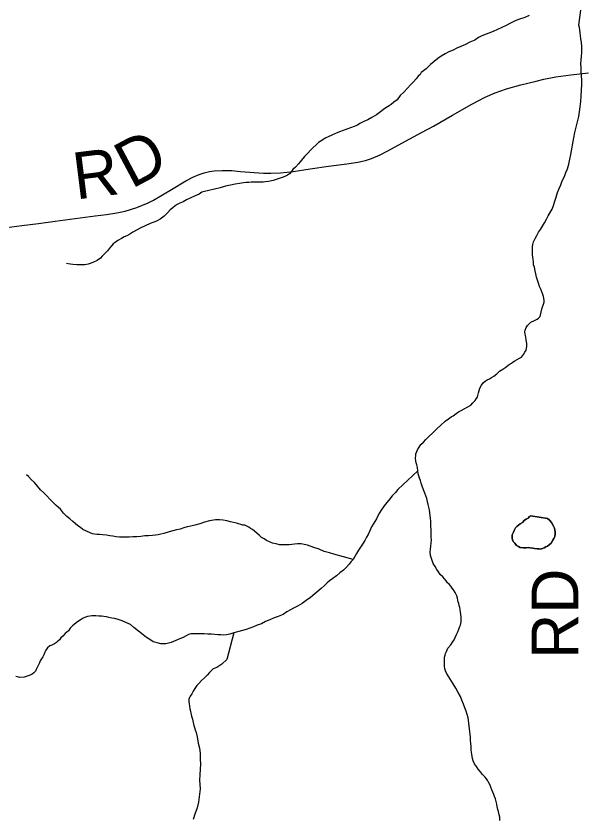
# Model space of a CAD drawing. Extents: x 103424 to 290657, y 38711 to 110967.
# Drawn here: x 115901 to 119588, y 79687 to 84863 of the extents above; entities that cross this region are included whole.
import ezdxf

# ---------------------------------------------------------------- set-up
doc = ezdxf.new("R2010")
doc.units = 0
for name, color, linetype in [('GM_X_Minor_Lake', 7, 'Continuous'), ('GM_X_Minor_River', 7, 'Continuous'), ('GM_X_Township_Road', 7, 'Continuous'), ('GM_X_Township_Road_Text', 7, 'Continuous')]:
    doc.layers.add(name, color=color, linetype=linetype)

msp = doc.modelspace()

# ---------------------------------------------------------------- linework, layer by layer
at = {"layer": 'GM_X_Minor_Lake'}
for points in [[(119225.9, 81636.5), (119217.7, 81632.3), (119207.7, 81622.1), (119195.6, 81615.9), (119185.6, 81607.8), (119171.7, 81593.5), (119157.6, 81585.3), (119145.6, 81577.1), (119135.6, 81568.9), (119127.6, 81558.7), (119117.7, 81542.4), (119113.8, 81530.3), (119105.9, 81514), (119104.2, 81491.8), (119106.3, 81481.7), (119112.5, 81471.7), (119122.7, 81459.7), (119133, 81445.6), (119145.2, 81437.7), (119157.4, 81431.7), (119177.6, 81429.9), (119195.8, 81430.1), (119207.9, 81432.2), (119220, 81430.3)], [(119225.9, 81636.5), (119332.9, 81619.3), (119345.2, 81609.3), (119359.5, 81593.3), (119369.8, 81575.2), (119378.1, 81557.1), (119380.3, 81545), (119382.4, 81533), (119382.6, 81518.8), (119380.7, 81502.6), (119374.8, 81490.5), (119366.9, 81480.3), (119357, 81460), (119345, 81449.8), (119333, 81441.6), (119322.9, 81437.4), (119310.9, 81429.2), (119300.9, 81425.1), (119288.8, 81420.9), (119278.7, 81422.8), (119266.5, 81424.7), (119250.3, 81426.6), (119238.2, 81428.5), (119220, 81430.3), (119207.9, 81432.2), (119195.8, 81430.1), (119177.6, 81429.9), (119157.4, 81431.7), (119145.2, 81437.7), (119133, 81445.6), (119122.7, 81459.7), (119112.5, 81471.7), (119106.3, 81481.7), (119104.2, 81491.8), (119105.9, 81514), (119113.8, 81530.3), (119117.7, 81542.4), (119127.6, 81558.7), (119135.6, 81568.9), (119145.6, 81577.1), (119157.6, 81585.3), (119171.7, 81593.5), (119185.6, 81607.8), (119195.6, 81615.9), (119207.7, 81622.1), (119217.7, 81632.3), (119225.9, 81636.5)], [(119220, 81430.3), (119238.2, 81428.5), (119250.3, 81426.6), (119266.5, 81424.7), (119278.7, 81422.8), (119288.8, 81420.9), (119300.9, 81425.1), (119310.9, 81429.2), (119322.9, 81437.4), (119333, 81441.6), (119345, 81449.8), (119357, 81460), (119366.9, 81480.3), (119374.8, 81490.5), (119380.7, 81502.6), (119382.6, 81518.8), (119382.4, 81533), (119380.3, 81545), (119378.1, 81557.1), (119369.8, 81575.2), (119359.5, 81593.3), (119345.2, 81609.3), (119332.9, 81619.3), (119225.9, 81636.5)]]:
    msp.add_lwpolyline(points, dxfattribs=at)
at = {"layer": 'GM_X_Minor_River'}
for points in [[(119308.2, 83053.3), (119304.1, 83065.4), (119295.8, 83081.4), (119289.5, 83099.6), (119281.2, 83117.7), (119274.9, 83137.8), (119268.7, 83158), (119262.4, 83178.1), (119258.1, 83198.2), (119253.8, 83218.4), (119249.5, 83242.6), (119243.3, 83256.7), (119243.1, 83272.8), (119240.8, 83293), (119238.6, 83307.1), (119236.5, 83321.3), (119236.3, 83333.4), (119236.2, 83345.5), (119236, 83359.6), (119235.8, 83373.8), (119237.7, 83387.9), (119243.6, 83404.1), (119253.4, 83426.5), (119263.3, 83446.8), (119275.2, 83467.1), (119287.1, 83485.4), (119301, 83505.7), (119312.8, 83528.1), (119326.7, 83550.4), (119338.6, 83572.8), (119350.4, 83595.1), (119362.3, 83615.4), (119372.1, 83639.7), (119379.9, 83668.1), (119389.7, 83694.5), (119397.4, 83722.8), (119409.2, 83749.2), (119419, 83773.5), (119428.8, 83799.9), (119442.7, 83826.3), (119452.5, 83852.6), (119462.3, 83877), (119470, 83907.4), (119477.7, 83937.7), (119483.4, 83968.1), (119502.4, 84077.4), (119510, 84111.8), (119517.7, 84146.2), (119527.4, 84180.7), (119535.1, 84213.1), (119540.8, 84243.4), (119544.5, 84275.8), (119548.1, 84310.1), (119549.8, 84344.5), (119553.3, 84387), (119554.9, 84419.3), (119554.6, 84447.6), (119552.3, 84475.8), (119549.9, 84504.1), (119549.6, 84530.3), (119549.3, 84554.6), (119551.1, 84580.9), (119552.8, 84603.1), (119554.6, 84625.3), (119554.3, 84645.5), (119554.1, 84665.7), (119551.8, 84694), (119549.5, 84716.2), (119547.2, 84736.4), (119545, 84754.5), (119542.8, 84772.7), (119540.6, 84788.8), (119536.4, 84802.9), (119549.4, 84900)], [(119214.5, 84866.4), (119186.4, 84854), (119146.1, 84839.4), (119120, 84829.1), (119093.9, 84816.7), (119065.8, 84802.3), (119037.7, 84787.9), (119009.6, 84775.5), (118983.4, 84763.1), (118909, 84734.1), (118887, 84723.7), (118864.9, 84707.4), (118830.8, 84692.9), (118802.7, 84678.5), (118774.5, 84666.1), (118748.4, 84655.7), (118724.3, 84643.3), (118696.2, 84630.9), (118672.1, 84618.6), (118646, 84604.2), (118624, 84587.8), (118602, 84569.4), (118577.9, 84549), (118550, 84522.4), (118532, 84508.1), (118518, 84497.9), (118510, 84485.7), (118498, 84473.4), (118486.1, 84457.1), (118468.1, 84438.8), (118448.2, 84418.4), (118428.3, 84396), (118406.3, 84371.5), (118382.4, 84349), (118362.5, 84322.6), (118340.4, 84306.2), (118324.4, 84291.9), (118310.4, 84283.7), (118300.4, 84277.5), (118288.4, 84269.3), (118274.3, 84259.1), (118254.3, 84244.7), (118228.3, 84224.3), (118198.2, 84207.8), (118172.1, 84193.4), (118148, 84181.1), (118121.9, 84168.7), (118105.9, 84158.4), (118083.7, 84150.1), (118061.6, 84141.8), (118037.5, 84131.5), (117989.2, 84114.9), (117965.1, 84104.5), (117916.9, 84083.8), (117896.8, 84073.5), (117876.8, 84059.2), (117854.7, 84046.8), (117802.7, 83997.8), (117784.8, 83977.5), (117762.9, 83955), (117744.9, 83932.6), (117725, 83908.2), (117705.1, 83887.8), (117689.1, 83871.5), (117679.1, 83859.2), (117667.2, 83845), (117653.2, 83834.8), (117637.1, 83826.5), (117619, 83820.3), (117600.9, 83814), (117580.8, 83807.8), (117560.7, 83801.5), (117532.5, 83795.2), (117510.3, 83792.9), (117496.2, 83790.8), (117480, 83790.6)], [(117480, 83790.6), (117461.8, 83790.4), (117435.6, 83790.2), (117419.4, 83790), (117405.3, 83787.8), (117387.1, 83787.7), (117369, 83785.5), (117344.8, 83781.2), (117316.6, 83776.9), (117286.4, 83770.5), (117254.1, 83764.1), (117219.9, 83753.7), (117183.6, 83745.2), (117145.4, 83736.8), (117119.2, 83730.5), (117101.1, 83726.2), (117083, 83713.9), (117056.9, 83701.6), (117030.8, 83689.2), (117002.7, 83676.8), (116980.6, 83664.4), (116958.5, 83654.1), (116942.4, 83645.9), (116928.4, 83637.7), (116914.4, 83625.4), (116896.4, 83611.1), (116878.4, 83592.7), (116858.5, 83570.3), (116832.4, 83551.9), (116808.4, 83539.5), (116790.3, 83531.2), (116768.2, 83522.9), (116701.9, 83494), (116683.8, 83481.7), (116655.7, 83467.3), (116635.7, 83454.9), (116617.6, 83444.7), (116599.5, 83436.4), (116581.5, 83426.1), (116559.4, 83413.8), (116541.4, 83401.5), (116527.3, 83391.2), (116519.4, 83381.1), (116505.4, 83364.8), (116491.5, 83346.4), (116475.5, 83330.1), (116465.5, 83321.9), (116457.6, 83311.8), (116445.6, 83299.5), (116425.6, 83285.2), (116397.5, 83270.8), (116367.3, 83260.4), (116345.1, 83256.1), (116327, 83255.9), (116310.8, 83255.8), (116292.6, 83257.6), (116268.3, 83259.4), (116238, 83263.1), (116227.8, 83265.6)], [(118607.4, 81309.1), (118595.1, 81329.2), (118578.3, 81381.5), (118576.1, 81403.7), (118577.9, 81421.9), (118579.7, 81440.1), (118581.4, 81462.4), (118583.2, 81480.6), (118583, 81500.8), (118582.8, 81521), (118582.5, 81545.2), (118580.2, 81571.4), (118579.8, 81601.7), (118575.4, 81638), (118570.9, 81674.4), (118562.4, 81710.6), (118553.9, 81748.9), (118541.4, 81783.1), (118526.8, 81821.4), (118518.4, 81847.6), (118512.1, 81865.7), (118505.9, 81879.8), (118501.7, 81893.9), (118497.5, 81908), (118495.3, 81926.1), (118493, 81948.3), (118488.7, 81966.4), (118484.6, 81978.5), (118482.4, 81990.6), (118480.2, 82010.8), (118482, 82022.9), (118483.9, 82037.1), (118489.8, 82051.3), (118493.7, 82063.5), (118503.6, 82079.7), (118515.5, 82098), (118531.5, 82112.3), (118547.5, 82128.6), (118565.4, 82147), (118595.4, 82173.5), (118619.4, 82198), (118645.3, 82222.5), (118671.3, 82247), (118693.3, 82263.4), (118711.4, 82275.7), (118723.4, 82281.9), (118743.4, 82298.2), (118757.4, 82308.5), (118775.5, 82316.7), (118837.7, 82351.7), (118851.7, 82366), (118865.7, 82380.3), (118873.6, 82392.5), (118881.6, 82402.6), (118883.5, 82412.8), (118887.3, 82431), (118891.2, 82445.2), (118897, 82461.4), (118906.9, 82479.7), (118918.8, 82495.9), (118930.8, 82506.2), (118942.9, 82514.4), (118959, 82520.6), (118971, 82528.8), (118987, 82539), (119005, 82553.4), (119023, 82569.7), (119045.1, 82584), (119063.1, 82596.3), (119079.1, 82608.6), (119091.1, 82616.8), (119101.2, 82623), (119111.2, 82631.2), (119123.2, 82637.3), (119137.3, 82645.6), (119153.3, 82653.8), (119165.4, 82660), (119179.3, 82678.3), (119187.2, 82692.5), (119195.1, 82706.7), (119198.9, 82729), (119198.7, 82749.2), (119196.4, 82771.4), (119194.1, 82791.6), (119189.9, 82809.7), (119187.7, 82823.8), (119189.6, 82836), (119195.4, 82852.2), (119203.4, 82864.4), (119213.4, 82874.6), (119225.3, 82886.8), (119249.5, 82897.2), (119265.5, 82905.4), (119275.5, 82911.6), (119285.5, 82923.8), (119299, 82978.5), (119304.8, 82996.7), (119310.7, 83014.9), (119312.6, 83027.1), (119310.4, 83041.2), (119308.2, 83053.3)], [(118077.8, 81354.3), (117954.2, 81389.4), (117925.8, 81397.3), (117891.4, 81407), (117858.9, 81420.8), (117824.4, 81432.6), (117783.9, 81446.3), (117761.6, 81452.2), (117741.4, 81456), (117719.1, 81455.8), (117699, 81453.6), (117682.8, 81451.4), (117664.7, 81449.2), (117650.5, 81449), (117634.4, 81448.9), (117620.3, 81448.8), (117602.1, 81450.6), (117581.8, 81456.4), (117557.5, 81460.2), (117537.2, 81468.1), (117518.9, 81478), (117502.7, 81488), (117486.4, 81497.9), (117470.1, 81511.9), (117427.3, 81547.8), (117415, 81555.8), (117404.8, 81563.8), (117390.6, 81569.7), (117378.5, 81575.6), (117366.3, 81577.5), (117352.1, 81581.4), (117338, 81585.3), (117323.8, 81589.2), (117305.6, 81593.1), (117285.3, 81598.9), (117263, 81604.8), (117238.7, 81608.6), (117214.5, 81610.4), (117188.2, 81610.1), (117149.9, 81603.6), (117117.7, 81595.2), (117087.5, 81584.8), (117055.3, 81576.4), (117029.1, 81570.1), (117007, 81565.9), (116984.8, 81559.6), (116960.7, 81551.3), (116936.5, 81547), (116914.4, 81540.7), (116890.2, 81532.4), (116856, 81521.9), (116835.9, 81517.7), (116819.8, 81513.5), (116801.6, 81511.3), (116781.4, 81509.1), (116757.2, 81506.8), (116733, 81506.6), (116706.8, 81504.3), (116680.5, 81502), (116656.3, 81501.8), (116632.1, 81499.5), (116611.9, 81499.3), (116587.7, 81499.1), (116569.5, 81498.9), (116547.3, 81500.7), (116527, 81504.5), (116506.8, 81508.4), (116484.5, 81512.2), (116460.3, 81514), (116440, 81515.8), (116421.9, 81515.6), (116407.7, 81517.5), (116395.6, 81521.4), (116379.3, 81527.3), (116332.6, 81549), (116316.3, 81561), (116300, 81573), (116283.7, 81586.9), (116267.4, 81600.9), (116249, 81616.9), (116228.7, 81632.8), (116208.2, 81652.9), (116187.7, 81678.9), (116159.2, 81702.9), (116138.7, 81724.9), (116118.3, 81744.9), (116099.9, 81764.9), (116079.5, 81784.9), (116059, 81804.9), (116040.6, 81828.9), (116020.1, 81850.9), (115999.7, 81870.9), (115981.3, 81891), (115968.5, 81902.1)], [(118495.3, 81926.1), (118367.4, 81805.6), (118351.5, 81787.3), (118329.5, 81764.9), (118307.6, 81738.4), (118285.7, 81709.9), (118263.9, 81679.4), (118244, 81648.9), (118228.2, 81618.4), (118208.4, 81581.9), (118196.5, 81565.6), (118190.6, 81551.4), (118182.7, 81535.2), (118174.9, 81516.9), (118165, 81498.6), (118153.1, 81478.3), (118139.2, 81453.9), (118125.3, 81433.6), (118113.4, 81415.3), (118099.6, 81392.9), (118089.7, 81374.6), (118077.8, 81354.3), (118063.8, 81340.1), (118051.9, 81323.8), (118035.9, 81305.4), (118016, 81287), (117991.9, 81268.6), (117969.9, 81250.2), (117945.9, 81231.8), (117925.9, 81217.5), (117909.9, 81203.2), (117889.9, 81184.8), (117871.9, 81168.4), (117801.9, 81109.2), (117773.9, 81090.7), (117747.8, 81070.2), (117719.8, 81053.8), (117693.6, 81041.4), (117673.6, 81029.1), (117649.5, 81016.8), (117625.5, 81000.4), (117593.3, 80987.9), (117567.2, 80977.6), (117541.1, 80965.2), (117512.9, 80954.8), (117486.8, 80940.4), (117458.6, 80930), (117434.5, 80919.7), (117410.4, 80911.4), (117386.3, 80903), (117364.1, 80896.8), (117340, 80890.5), (117307.7, 80882.1), (117281.6, 80873.7), (117259.4, 80869.4), (117241.3, 80867.2), (117223.1, 80869.1), (117204.9, 80868.9), (117184.7, 80870.7), (117162.4, 80872.5), (117140.2, 80872.3), (117116, 80874.1), (117093.7, 80875.9), (117073.5, 80875.7), (117045.3, 80875.4), (117029.1, 80875.2), (117015, 80871.1), (116999, 80862.8), (116980.9, 80852.5), (116962.8, 80844.3), (116948.8, 80838.1), (116932.7, 80831.8), (116918.6, 80825.7), (116902.5, 80819.4), (116886.4, 80815.2), (116868.3, 80811), (116854.2, 80810.9), (116836, 80810.7), (116811.7, 80816.5), (116787.4, 80824.3), (116765, 80838.3), (116744.6, 80852.2), (116722.2, 80868.1), (116661.1, 80916), (116640.7, 80936), (116610.2, 80947.8), (116585.9, 80959.7), (116561.5, 80967.5), (116539.2, 80973.4), (116519, 80977.2), (116500.8, 80981.1), (116484.6, 80984.9), (116468.4, 80986.8), (116452.2, 80988.7), (116436.1, 80988.5), (116415.9, 80990.3), (116391.6, 80992.1), (116377.5, 80989.9)], [(119026.3, 79671), (119026.1, 79691.2), (119021.9, 79707.3), (119017.6, 79727.5), (119013.4, 79741.6), (119009.1, 79759.7), (119006.9, 79775.8), (119000.7, 79794), (118996.4, 79810.1), (118990.2, 79824.2), (118986, 79838.2), (118979.8, 79852.3), (118973.5, 79868.4), (118967.3, 79884.5), (118963.1, 79898.6), (118954.9, 79912.7), (118948.6, 79926.8), (118938.4, 79938.8), (118928.1, 79952.8), (118913.8, 79966.8), (118899.5, 79984.8), (118885.2, 80000.9), (118874.8, 80018.9), (118862.5, 80037), (118854.2, 80055.1), (118848, 80071.2), (118843.6, 80097.4), (118841.3, 80123.6), (118841.1, 80147.9), (118838.8, 80168.1), (118836.5, 80188.2), (118836.3, 80208.4), (118834.1, 80226.6), (118831.8, 80244.8), (118829.6, 80262.9), (118827.4, 80281.1), (118825.2, 80297.2), (118822.9, 80317.4), (118820.7, 80333.5), (118814.4, 80353.7), (118808.1, 80375.8), (118799.8, 80398), (118791.4, 80422.1), (118781, 80446.3), (118770.7, 80470.4), (118756.2, 80496.5), (118741.8, 80524.6), (118723.3, 80552.7), (118680.1, 80621), (118673.8, 80637.1), (118669.6, 80651.2), (118667.4, 80665.3), (118667.2, 80685.5), (118667, 80705.7), (118668.8, 80723.9), (118672.6, 80738.1), (118674.5, 80748.2), (118680.5, 80760.4), (118690.3, 80782.7), (118708.2, 80803.1), (118720.1, 80821.4), (118730.1, 80835.6), (118738, 80851.9), (118745.8, 80870.1), (118753.7, 80888.4), (118759.6, 80904.6), (118765.5, 80918.8), (118771.4, 80931), (118773.3, 80941.1), (118775.2, 80953.2), (118775, 80971.4), (118774.8, 80985.5), (118772.6, 80999.7), (118772.4, 81015.8), (118770.2, 81032), (118766, 81046), (118763.8, 81058.2), (118759.7, 81070.2), (118755.5, 81082.3), (118753.3, 81092.4), (118751.2, 81104.5), (118747, 81120.6), (118740.8, 81132.7), (118736.6, 81142.7), (118726.3, 81158.8), (118718.1, 81170.8), (118707.9, 81182.8), (118697.6, 81194.9), (118687.4, 81204.9), (118679.2, 81216.9), (118668.9, 81230.9), (118656.7, 81242.9), (118640.3, 81258.9), (118630.1, 81275), (118617.8, 81291), (118607.4, 81309.1)], [(116377.5, 80989.9), (116363.4, 80987.8), (116349.3, 80981.6), (116335.2, 80975.4), (116321.2, 80967.2), (116305.2, 80956.9), (116289.1, 80946.6), (116277.1, 80936.4), (116265.1, 80926.2), (116251.2, 80911.9), (116239.3, 80893.6), (116219.3, 80877.3), (116203.3, 80860.9), (116191.3, 80848.7), (116181.4, 80836.5), (116171.3, 80828.3), (116163.4, 80818.1), (116149.4, 80809.9), (116131.3, 80801.6), (116119.2, 80797.5), (116103.2, 80785.2), (116093.3, 80768.9), (116087.4, 80756.8), (116081.5, 80740.5), (116073.6, 80726.3), (116065.6, 80714.1), (116057.7, 80701.9), (116051.8, 80687.7), (116032.1, 80645.1), (116026.2, 80635), (116016.2, 80622.7), (116006.2, 80614.6), (115992.1, 80608.3), (115974, 80602.1), (115953.9, 80595.8), (115925.7, 80593.5), (115911.5, 80597.4), (115899.4, 80599.3)], [(117307.7, 80882.1), (117263.3, 80709.9), (117229.3, 80679.3), (117197.2, 80658.7), (117175.1, 80648.4), (117165.1, 80640.2), (117151.2, 80626), (117135.2, 80607.6), (117117.2, 80591.3), (117099.3, 80572.9), (117081.3, 80554.6), (117069.3, 80542.3), (117055.4, 80522), (117045.5, 80505.7), (117035.6, 80487.5), (117025.7, 80473.2), (117021.8, 80463.1), (117017.9, 80452.9), (117018, 80436.8), (117018.2, 80424.7), (117020.4, 80408.5), (117022.6, 80390.4), (117026.8, 80376.3), (117029, 80362.1), (117033.3, 80344), (117039.6, 80323.9), (117045.9, 80303.7), (117050.1, 80283.6), (117054.3, 80269.5), (117058.5, 80255.4), (117064.8, 80237.3), (117071.2, 80211.1), (117077.7, 80168.7), (117086.2, 80136.5), (117090.6, 80104.2), (117091, 80065.8), (117091.4, 80033.5), (117089.7, 80001.2), (117088.2, 79964.8), (117086.5, 79930.4), (117088.9, 79902.2), (117089.2, 79873.9), (117080.1, 79789), (117070.4, 79752.5), (117056.7, 79712), (117045, 79677.5)]]:
    msp.add_lwpolyline(points, dxfattribs=at)
at = {"layer": 'GM_X_Township_Road'}
msp.add_lwpolyline([(115774.7, 83488.8), (115938.3, 83510.3), (116045.6, 83524.5), (116153, 83538.6), (116282.4, 83556.3), (116411.8, 83574), (116484.3, 83582.6), (116553, 83592), (116606.5, 83603), (116680.9, 83625.8), (116753.9, 83655.9), (116789, 83674.5), (116904.2, 83743.7), (116997.5, 83799.8), (117042.8, 83822.7), (117084.4, 83839.3), (117116.9, 83850.9), (117149.6, 83858.6), (117181.6, 83863.5), (117232.6, 83866.2), (117294.1, 83864.6), (117350.1, 83860.1), (117498.5, 83849.3), (117546.7, 83848.4), (117608, 83851.1), (117690.2, 83860), (117799.7, 83875.8), (117918.8, 83892.6), (118037.8, 83909.4), (118109.3, 83919.6), (118157.6, 83929.8), (118196.8, 83942.2), (118253.5, 83967.4), (118298.2, 83990.5), (118443.2, 84069.3), (118519.8, 84110.9), (118596.4, 84152.4), (118720.3, 84223.2), (118844.2, 84294), (118929.7, 84337.9), (118995.4, 84365.9), (119068, 84391.9), (119160.2, 84418.7), (119260.3, 84442.4), (119310, 84454.7), (119386.8, 84469.5), (119483.7, 84483.4), (119598.7, 84496.6)], dxfattribs=at)

# ---------------------------------------------------------------- texts
at = {"layer": 'GM_X_Township_Road_Text'}
for s, height, rotation, p in [('D', 301.9, 28.0436, (116646.2, 83744.2)), ('R', 301.9, 7.1178, (116288, 83677.9)), ('RD', 301.87, 90, (119532.1, 80713))]:
    msp.add_text(s, height=height, rotation=rotation, dxfattribs=at).set_placement(p)

doc.saveas('drawing.dxf')
